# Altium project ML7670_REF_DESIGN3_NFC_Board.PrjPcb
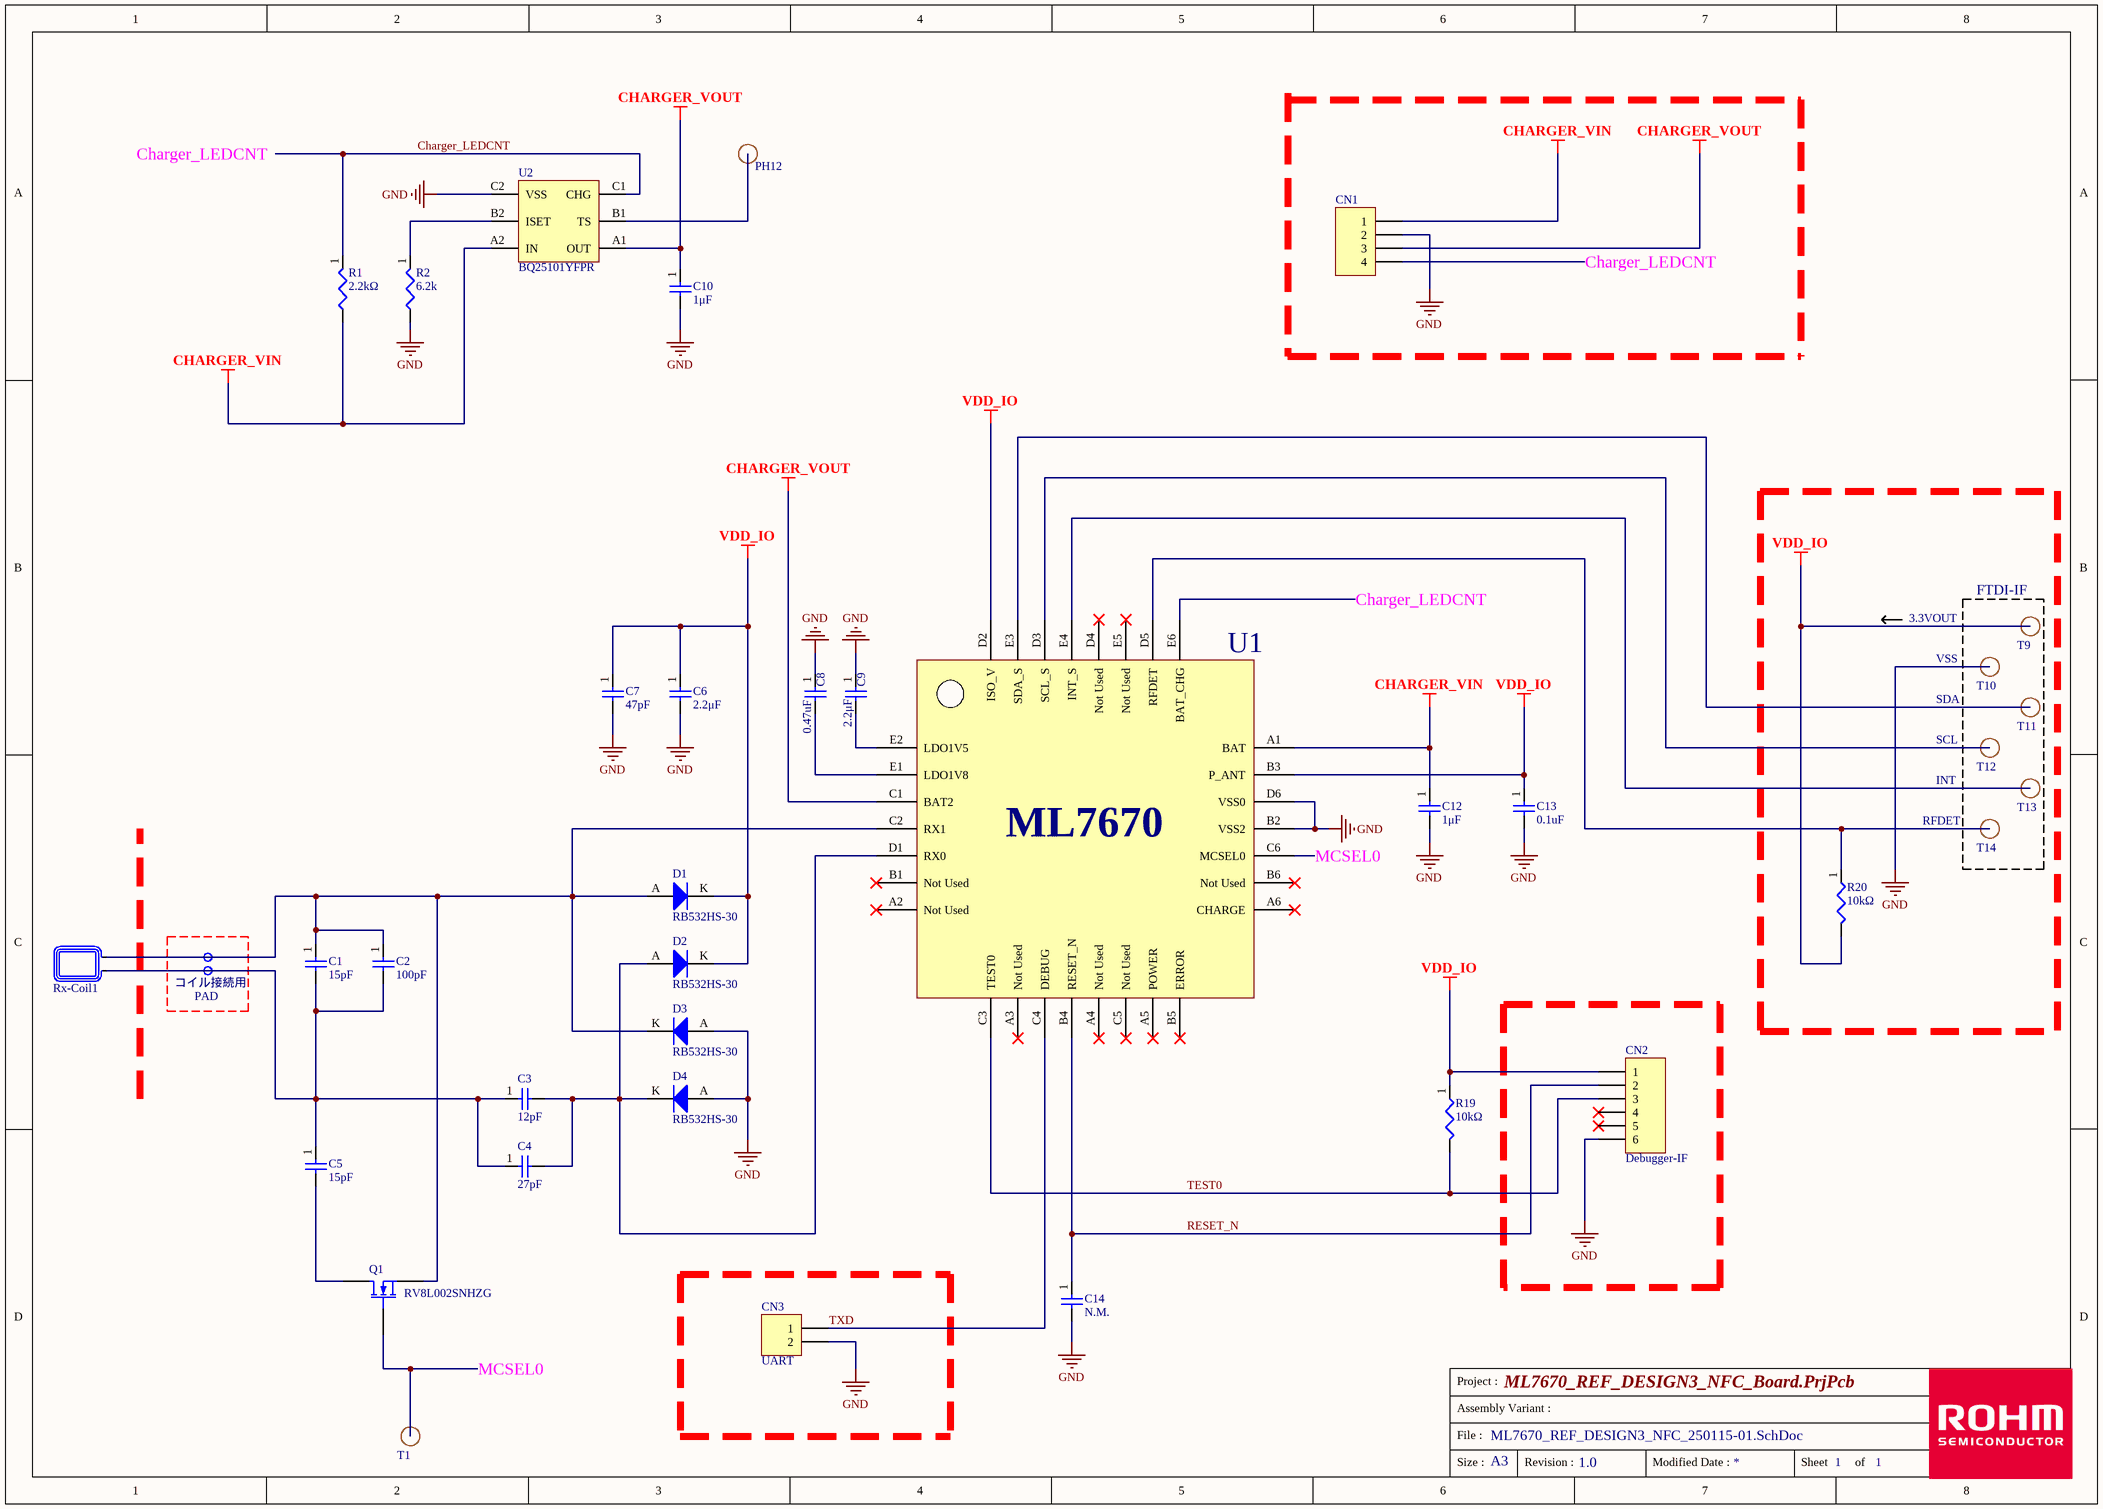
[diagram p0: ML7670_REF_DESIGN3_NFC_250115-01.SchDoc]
1 sheet, 36 parts. Net scope: global (net labels, ports and power ports of the same name join across sheets).
Board file: ML7670_REF_D3_NFC_final.PcbDoc

## Sheet ML7670_REF_DESIGN3_NFC_250115-01.SchDoc: ML7801_TX_Board
size A3; Revision: 1.0; SheetNumber: 1; SheetTotal: 1; Application: NFC TX

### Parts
C1  value 15pF  [CC1005_02]  (hidden comment: Cap)
C2  value 100pF  [CC1005_02]  (hidden comment: Cap)
C3  value 12pF  [CC1005_02]  (hidden comment: Cap)
C4  value 27pF  [CC1005_02]  (hidden comment: Cap)
C5  value 15pF  [CC1005_02]  (hidden comment: Cap)
C6  value 2.2μF  [0603-1_00]  (hidden comment: Cap)
C7  value 47pF  [0603-1_00]  (hidden comment: Cap)
C8  value 0.47uF  [0603-1_00]  (hidden comment: Cap)
C9  value 2.2μF  [0603-1_00]  (hidden comment: Cap)
C10  value 1μF  [0603-1_00]  (hidden comment: Cap)
C12  value 1μF  [0603-1_00]  (hidden comment: Cap)
C13  value 0.1uF  [0603-1_00]  (hidden comment: Cap)
C14  value N.M.  [0603-1_00]  (hidden comment: Cap)
CN1  4pin Pin header  [J4P-2.54_01]  (value not drawn)
CN2  Note: Debugger-IF  [CN6_XB-1-5]  (hidden comment: MHDR1X6)
CN3  Note: UART  [JP2-2.54_01]  (hidden comment: Header 2)
D1  RB532HS-30  [SOD-962_12_00]
D2  RB532HS-30  [SOD-962_12_00]
D3  RB532HS-30  [SOD-962_12_00]
D4  RB532HS-30  [SOD-962_12_00]
PH12  (no value)  [TH0.8_1.4_00]
Q1  RV8L002SNHZG  [DFN1010-3W_GSD]
R1  2.2kΩ  [0603-1_01]
R2  6.2k  [0603-1_01]
R19  10kΩ  [0603-1_01]
R20  10kΩ  [0603-1_01]
Rx-Coil1  -  [Tx-Coil1]  (value not drawn)
T1  (no value)  [TH0.8_1.4_00]
T9  (no value)  [TH0.8_1.4_00]
T10  (no value)  [TH0.8_1.4_00]
T11  (no value)  [TH0.8_1.4_00]
T12  (no value)  [TH0.8_1.4_00]
T13  (no value)  [TH0.8_1.4_00]
T14  (no value)  [TH0.8_1.4_00]
U1  -  [ML7670_WL-CSP30_00]  (value not drawn)
U2  BQ25101YFPR  [DSBGA (YFP)]

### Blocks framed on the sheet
FTDI-IF: T9-T14

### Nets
CHARGER_VIN: C12.1 CN1.1 R1.2 U1.A1(BAT) U2.A2(IN)
CHARGER_VOUT: C10.1 CN1.3 U1.C1(BAT2) U2.A1(OUT)
GND: C6.2 C7.2 C8.1 C9.1 C10.2 C12.2 C13.2 C14.2 CN1.2 CN2.6 CN3.2 D3.A D4.A R2.2 T10.1 U1.B2(VSS2) U1.D6(VSS0) U2.C2(VSS)
VDD_IO: C6.1 C7.1 C13.1 CN2.1 D1.K D2.K R19.1 R20.2 T9.1 U1.B3(P_ANT) U1.D2(ISO_V)
Charger_LEDCNT: CN1.4 R1.1 U1.E6(BAT_CHG) U2.C1(CHG)
MCSEL0: Q1.G T1.1 U1.C6(MCSEL0)
RESET_N: C14.1 CN2.2 U1.B4(RESET_N)
TEST0: CN2.3 R19.2 U1.C3(TEST0)
TXD: CN3.1 U1.C4(DEBUG)
NetC1_1: C1.1 C2.1 D1.A D3.K Q1.S Rx-Coil1.1 U1.C2(RX1)
NetC1_2: C1.2 C2.2 C3.1 C4.1 C5.1 Rx-Coil1.2
NetC3_2: C3.2 C4.2 D2.A D4.K U1.D1(RX0)
NetC5_2: C5.2 Q1.D
NetC8_2: C8.2 U1.E1(LDO1V8)
NetC9_2: C9.2 U1.E2(LDO1V5)
NetPH12_1: PH12.1 U2.B1(TS)
NetR2_1: R2.1 U2.B2(ISET)
NetR20_1: R20.1 T14.1 U1.D5(RFDET)
NetT11_1: T11.1 U1.E3(SDA_S)
NetT12_1: T12.1 U1.D3(SCL_S)
NetT13_1: T13.1 U1.E4(INT_S)

Not connected (* = marked no-connect by the designer): CN2 4* 5*; U1 A2(Not_Used)* A3(Not_Used)* A4(Not_Used)* A5(POWER)* A6(CHARGE)* B1(Not_Used)* B5(ERROR)* B6(Not_Used)* C5(Not_Used)* D4(Not_Used)* E5(Not_Used)*

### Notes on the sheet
- 3.3VOUT
- (near T10) VSS
- SDA
- (near T12) SCL
- INT
- (near T14) RFDET
- コイル接続用
- PAD
- Labels drawn without touching a wire or pin: Charger_LEDCNT

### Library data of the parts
C1 = Cap: Capacitor
C2 = Cap: Capacitor; Part Number: GRM1555C1H180GA01#; Note: 50Vdc,20%; Maker: Murata
C3 = Cap: Capacitor; Part Number: GRM1555C2A121GE01#; Note: 100Vdc,2%; Maker: Murata
C4 = Cap: Capacitor; Part Number: GRM1555C1H3R9BA01#; Note: 50Vdc,2%; Maker: Murata
C5 = Cap: Capacitor; Part Number: GRM1555C2A150GE02#; Note: 100Vdc,2%
C6 = Cap: Capacitor; Part Number: GRM035R61C225ME01#; Note: 16Vdc,10%; Maker: Murata
C7 = Cap: Capacitor; Part Number: GRM0335C1H470FA01#; Note: 16Vdc,10%; Maker: Murata
C8 = Cap: Capacitor; Part Number: GRM033R60J474KE90#; Note: 6.3Vdc,10%; Maker: Murata
C9 = Cap: Capacitor; Part Number: GRM035R61C225ME01#; Note: 16Vdc,20%; Maker: Murata
C10 C12 = Cap: Capacitor; Part Number: GRM033R61C105ME15#; Note: 25Vdc,1%; Maker: Murata
C13 = Cap: Capacitor; Part Number: GRM033R61C104KE18#; Note: 25Vdc,10%; Maker: Murata
C14 = Cap: Capacitor; Part Number: GRM033R61C104KE18#; Note: 50Vdc,1%; Maker: Murata
CN1 = CN
CN2 = MHDR1X6: Header, 6-Pin; Part Number: XB-1-5-6P; Value: 6-Pin Header
CN3 = Header 2: Header, 2-Pin; Part Number: PH-1x2SG; Value: 2-Pin Header
D1-D4 = RB532
PH12 T1 T9-T14 = TP: Value: Small Pad
Q1 = MOSFET-N: N-Channel MOSFET; Part Number: RV8L002SNHZGG2CR; Maker: Rohm
R1 = Res3: Resistor; Part Number: ERJ-1GNJ222C; Maker: panasonic; Note: 0.05W,±5%, Pull-up
R2 = Res3: Resistor; Part Number: ERJ-1GNJ332C; Maker: panasonic; Note: 0.05W,±5%, Pull-up
R19 R20 = Res3: Resistor; Part Number: ERJ-1GNJ103C; Maker: Panasonic
Rx-Coil1 = NFC_Antenna: NFC Antenna; Part Number: 「S24-T6」
U1 = ML7670: NFC TX, WQFN40; Maker: Rohm; Note: WQFN-40pin
U2 = BQ25101

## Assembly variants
Variant of ML7670_REF_DESIGN3_NFC_Board: not fitted C1 C2 C3 C4 C10 C14 CN2 CN3 PH12 Rx-Coil1 T1 T9 T10 T11 T12 T13 T14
